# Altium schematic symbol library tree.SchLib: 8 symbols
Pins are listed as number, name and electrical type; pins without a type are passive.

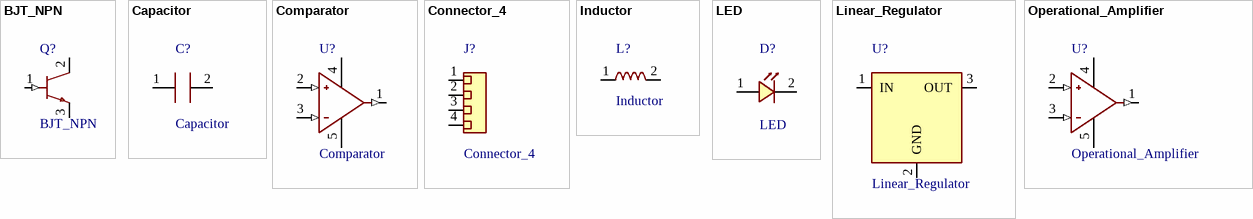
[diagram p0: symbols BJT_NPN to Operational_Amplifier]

## BJT_NPN
designator Q?
Conceptual NPN B/C/E; not a device pinout
pins: 1 B (in), 2 C, 3 E

## Capacitor
designator C?
Generic non-polarized capacitor
pins: 1 A, 2 B

## Comparator
designator U?
Conceptual comparator; not a device pinout
pins: 1 (out), 2 + (in), 3 - (in), 4 V+ (power), 5 V- (power)

## Connector_4
designator J?
Generic four-circuit connector
pins: 1 Passive, 2 Passive, 3 Passive, 4 Passive

## Inductor
designator L?
Generic inductor
pins: 1 A, 2 B

## LED
designator D?
Generic light-emitting diode
pins: 1 A, 2 K

## Linear_Regulator
designator U?
Conceptual three-function linear regulator; not a device pinout
pins: 1 IN (power), 2 GND (power), 3 OUT (power)

## Operational_Amplifier
designator U?
Conceptual five-function op amp; not a device pinout
pins: 1 (out), 2 + (in), 3 - (in), 4 V+ (power), 5 V- (power)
